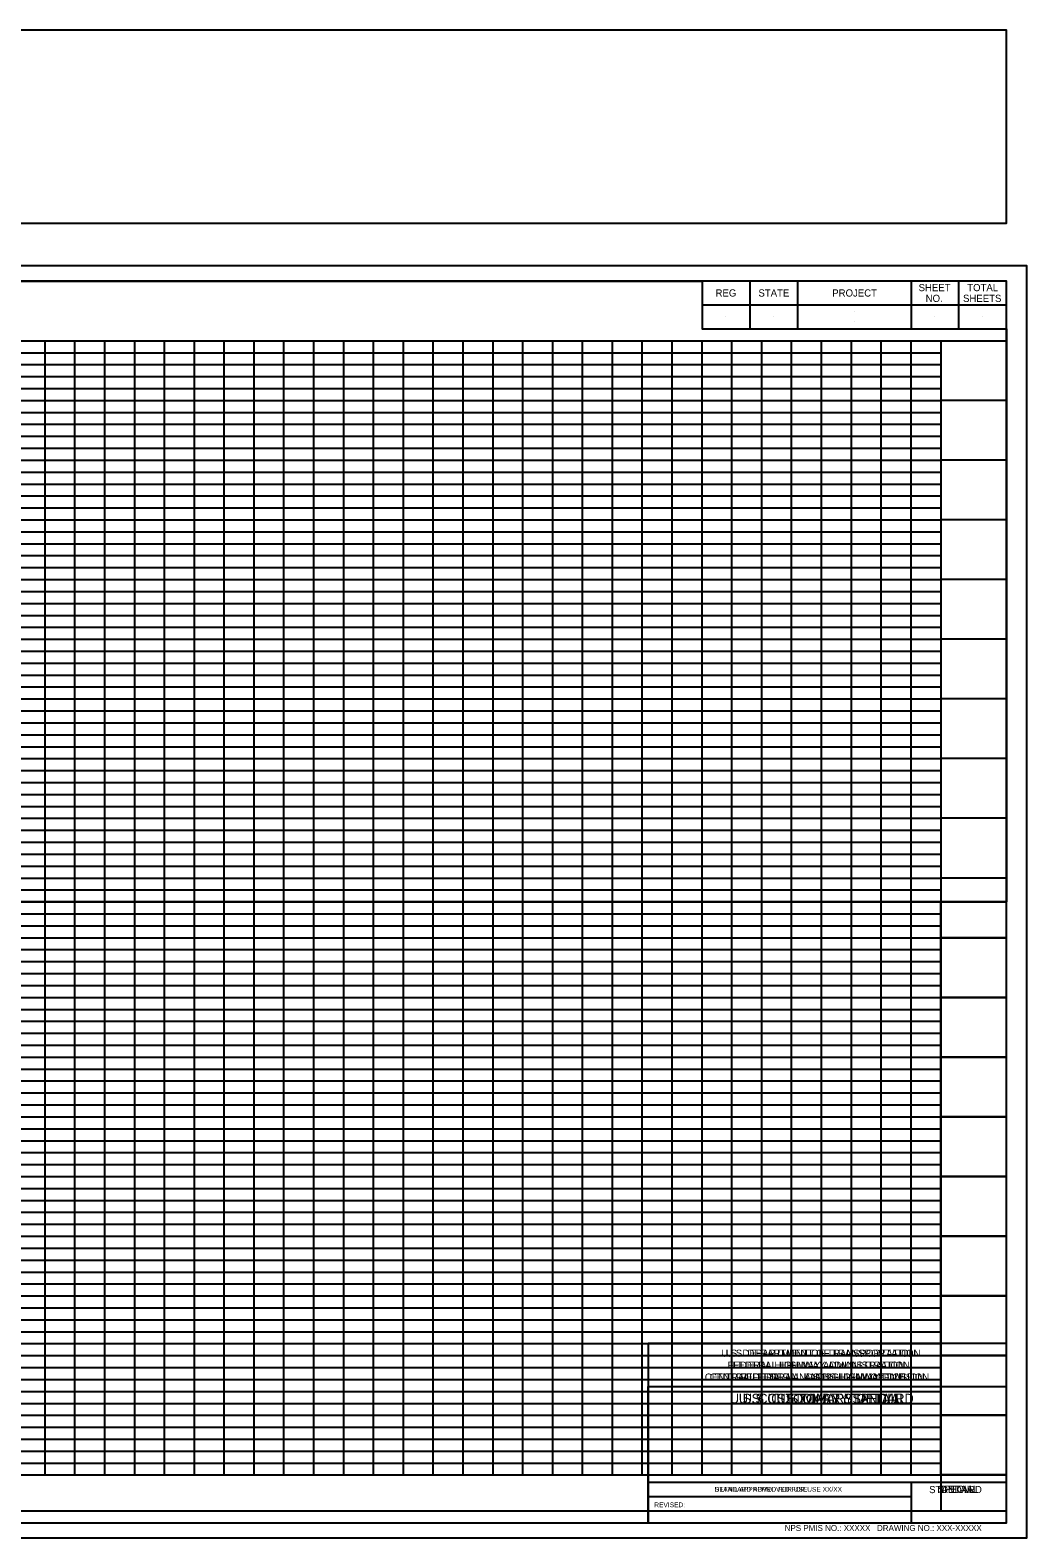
# Model space of a CAD drawing. Extents: x -87 to 1577, y -13 to 1250.
# Drawn here: x 742 to 1577, y -13 to 1250 of the extents above; entities that cross this region are included whole.
import ezdxf

# ---------------------------------------------------------------- set-up
doc = ezdxf.new("R2010")
doc.units = 0
for name, color, linetype in [('D_CFL_Clip_Boundary_1', 7, 'Continuous'), ('D_CFL_Clip_Boundary_2', 7, 'Continuous'), ('D_CFL_Sheet_Border_ PlotShape', 7, 'Continuous'), ('D_CFL_Sheet_Border_Base', 7, 'Continuous'), ('D_CFL_Sheet_Border_Box', 7, 'Continuous'), ('D_CFL_Sheet_Border_Detail', 7, 'Continuous'), ('D_CFL_Sheet_Border_General', 7, 'Continuous'), ('D_CFL_Sheet_Border_NPS_Pkg', 7, 'Continuous'), ('D_CFL_Sheet_Border_Plan_Plan', 7, 'Continuous'), ('D_CFL_Sheet_Border_PnP', 7, 'Continuous'), ('D_CFL_Sheet_Border_Profile', 7, 'Continuous'), ('D_CFL_Sheet_Border_Project_Info', 7, 'Continuous'), ('D_CFL_Sheet_Border_Special', 7, 'Continuous'), ('D_CFL_Sheet_Border_Standard', 7, 'Continuous')]:
    doc.layers.add(name, color=color, linetype=linetype)

msp = doc.modelspace()

# ---------------------------------------------------------------- linework, layer by layer
at = {"layer": 'D_CFL_Clip_Boundary_1'}
msp.add_lwpolyline([(0, 520), (0, 1040), (1305, 1040), (1305, 1000), (1560, 1000), (1560, 520)], close=True, dxfattribs=at)
at = {"layer": 'D_CFL_Clip_Boundary_2'}
msp.add_lwpolyline([(1505, 520), (55, 520), (55, 40), (1505, 40)], close=True, dxfattribs=at)
at = {"layer": 'D_CFL_Sheet_Border_ PlotShape'}
msp.add_line((1576.9, 1052.6), (1576.9, 1052.6), dxfattribs=at)
msp.add_lwpolyline([(-86.9, -12.7), (1576.9, -12.7), (1576.9, 1052.6), (-86.9, 1052.6)], close=True, dxfattribs=at)
at = {"layer": 'D_CFL_Sheet_Border_Base'}
for p, q in [((1345, 1040), (1345, 1000)), ((1385, 1040), (1385, 1000)), ((1480, 1040), (1480, 1000)), ((1520, 1000), (1520, 1040)), ((1305, 1020), (1560, 1020))]:
    msp.add_line(p, q, dxfattribs=at)
for points in [[(362.6, 1088.6), (1560, 1088.6), (1560, 1250.1), (362.6, 1250.1)], [(0, 0), (1560, 0), (1560, 1040), (0, 1040)]]:
    msp.add_lwpolyline(points, close=True, dxfattribs=at)
msp.add_lwpolyline([(1305, 1040), (1305, 1000), (1560, 1000)], dxfattribs=at)
at = {"layer": 'D_CFL_Sheet_Border_Box'}
for p, q in [((1260, 0), (1260, 114)), ((1260, 114), (1560, 114)), ((1410, 57), (1410, 57))]:
    msp.add_line(p, q, dxfattribs=at)
at = {"layer": 'D_CFL_Sheet_Border_Detail'}
for p, q in [((1260, 114), (1560, 114)), ((1410, 69), (1410, 69)), ((1260, 34), (1560, 34)), ((1480, 34), (1480, 0)), ((1260, 22), (1480, 22))]:
    msp.add_line(p, q, dxfattribs=at)
msp.add_lwpolyline([(1560, 150), (1260, 150), (1260, 0)], dxfattribs=at)
at = {"layer": 'D_CFL_Sheet_Border_General'}
for p, q in [((1260, 114), (1560, 114)), ((1410, 57), (1410, 57))]:
    msp.add_line(p, q, dxfattribs=at)
msp.add_lwpolyline([(1560, 150), (1260, 150), (1260, 0)], dxfattribs=at)
at = {"layer": 'D_CFL_Sheet_Border_Plan_Plan'}
for p, q in [((0, 520), (1560, 520)), ((1260, 0), (1260, 114)), ((1260, 114), (1560, 114)), ((1410, 57), (1410, 57))]:
    msp.add_line(p, q, dxfattribs=at)
at = {"layer": 'D_CFL_Sheet_Border_PnP'}
for p, q in [((0, 520), (1560, 520)), ((755, 40), (755, 520)), ((780, 40), (780, 520)), ((805, 40), (805, 520)), ((830, 40), (830, 520)), ((855, 40), (855, 520)), ((880, 40), (880, 520)), ((905, 40), (905, 520)), ((930, 40), (930, 520)), ((955, 40), (955, 520)), ((980, 40), (980, 520)), ((1005, 40), (1005, 520)), ((1030, 40), (1030, 520)), ((1055, 40), (1055, 520)), ((1080, 40), (1080, 520)), ((1105, 40), (1105, 520)), ((1130, 40), (1130, 520)), ((1155, 40), (1155, 520)), ((1180, 40), (1180, 520)), ((1205, 40), (1205, 520)), ((1230, 40), (1230, 520)), ((1255, 40), (1255, 520)), ((1280, 40), (1280, 520)), ((1305, 40), (1305, 520)), ((1330, 40), (1330, 520)), ((1355, 40), (1355, 520)), ((1380, 40), (1380, 520)), ((1405, 40), (1405, 520)), ((1430, 40), (1430, 520)), ((1455, 40), (1455, 520)), ((1480, 40), (1480, 520)), ((1505, 520), (1505, 10)), ((55, 510), (1505, 510)), ((55, 500), (1505, 500)), ((55, 490), (1505, 490)), ((55, 480), (1505, 480)), ((1505, 490), (1560, 490)), ((55, 470), (1505, 470)), ((55, 460), (1505, 460)), ((55, 450), (1505, 450)), ((55, 440), (1505, 440)), ((55, 430), (1505, 430)), ((1505, 440), (1560, 440)), ((55, 420), (1505, 420)), ((55, 410), (1505, 410)), ((55, 400), (1505, 400)), ((55, 390), (1505, 390)), ((55, 380), (1505, 380)), ((1505, 390), (1560, 390)), ((55, 370), (1505, 370)), ((55, 360), (1505, 360)), ((55, 350), (1505, 350)), ((55, 340), (1505, 340)), ((55, 330), (1505, 330)), ((1505, 340), (1560, 340)), ((55, 320), (1505, 320)), ((55, 310), (1505, 310)), ((55, 300), (1505, 300)), ((55, 290), (1505, 290)), ((55, 280), (1505, 280)), ((1505, 290), (1560, 290)), ((55, 270), (1505, 270)), ((55, 260), (1505, 260)), ((55, 250), (1505, 250)), ((55, 240), (1505, 240)), ((1505, 240), (1560, 240)), ((55, 230), (1505, 230)), ((55, 220), (1505, 220)), ((55, 210), (1505, 210)), ((55, 200), (1505, 200)), ((55, 190), (1505, 190)), ((1505, 190), (1560, 190)), ((55, 180), (1505, 180)), ((55, 170), (1505, 170)), ((55, 160), (1505, 160)), ((55, 150), (1505, 150)), ((55, 140), (1505, 140)), ((1505, 140), (1560, 140)), ((55, 130), (1505, 130)), ((55, 120), (1505, 120)), ((55, 110), (1505, 110)), ((55, 100), (1505, 100)), ((55, 90), (1505, 90)), ((1505, 90), (1560, 90)), ((55, 80), (1505, 80)), ((55, 70), (1505, 70)), ((55, 60), (1505, 60)), ((55, 50), (1505, 50)), ((55, 40), (1505, 40)), ((1505, 40), (1560, 40)), ((0, 10), (1560, 10))]:
    msp.add_line(p, q, dxfattribs=at)
at = {"layer": 'D_CFL_Sheet_Border_Profile'}
for p, q in [((0, 990), (1560, 990)), ((755, 40), (755, 990)), ((780, 40), (780, 990)), ((805, 40), (805, 990)), ((830, 40), (830, 990)), ((855, 40), (855, 990)), ((880, 40), (880, 990)), ((905, 40), (905, 990)), ((930, 40), (930, 990)), ((955, 40), (955, 990)), ((980, 40), (980, 990)), ((1005, 40), (1005, 990)), ((1030, 40), (1030, 990)), ((1055, 40), (1055, 990)), ((1080, 40), (1080, 990)), ((1105, 40), (1105, 990)), ((1130, 40), (1130, 990)), ((1155, 40), (1155, 990)), ((1180, 40), (1180, 990)), ((1205, 40), (1205, 990)), ((1230, 40), (1230, 990)), ((1255, 40), (1255, 990)), ((1280, 40), (1280, 990)), ((1305, 40), (1305, 990)), ((1330, 40), (1330, 990)), ((1355, 40), (1355, 990)), ((1380, 40), (1380, 990)), ((1405, 40), (1405, 990)), ((1430, 40), (1430, 990)), ((1455, 40), (1455, 990)), ((1480, 40), (1480, 990)), ((1505, 990), (1505, 10)), ((55, 980), (1505, 980)), ((55, 970), (1505, 970)), ((55, 960), (1505, 960)), ((55, 950), (1505, 950)), ((55, 940), (1505, 940)), ((1560, 940), (1505, 940)), ((55, 930), (1505, 930)), ((55, 920), (1505, 920)), ((55, 910), (1505, 910)), ((55, 900), (1505, 900)), ((55, 890), (1505, 890)), ((1560, 890), (1505, 890)), ((55, 880), (1505, 880)), ((55, 870), (1505, 870)), ((55, 860), (1505, 860)), ((55, 850), (1505, 850)), ((55, 840), (1505, 840)), ((1560, 840), (1505, 840)), ((55, 830), (1505, 830)), ((55, 820), (1505, 820)), ((55, 810), (1505, 810)), ((55, 800), (1505, 800)), ((55, 790), (1505, 790)), ((1560, 790), (1505, 790)), ((55, 780), (1505, 780)), ((55, 770), (1505, 770)), ((55, 760), (1505, 760)), ((55, 750), (1505, 750)), ((55, 740), (1505, 740)), ((1560, 740), (1505, 740)), ((55, 730), (1505, 730)), ((55, 720), (1505, 720)), ((55, 710), (1505, 710)), ((55, 700), (1505, 700)), ((55, 690), (1505, 690)), ((1560, 690), (1505, 690)), ((55, 680), (1505, 680)), ((55, 670), (1505, 670)), ((55, 660), (1505, 660)), ((55, 650), (1505, 650)), ((55, 640), (1505, 640)), ((1560, 640), (1505, 640)), ((55, 630), (1505, 630)), ((55, 620), (1505, 620)), ((55, 610), (1505, 610)), ((55, 600), (1505, 600)), ((55, 590), (1505, 590)), ((1560, 590), (1505, 590)), ((55, 580), (1505, 580)), ((55, 570), (1505, 570)), ((55, 560), (1505, 560)), ((55, 550), (1505, 550)), ((55, 540), (1505, 540)), ((1560, 540), (1505, 540)), ((55, 530), (1505, 530)), ((55, 520), (1505, 520)), ((55, 510), (1505, 510)), ((55, 500), (1505, 500)), ((55, 490), (1505, 490)), ((55, 480), (1505, 480)), ((1560, 490), (1505, 490)), ((55, 470), (1505, 470)), ((55, 460), (1505, 460)), ((55, 450), (1505, 450)), ((55, 440), (1505, 440)), ((55, 430), (1505, 430)), ((1560, 440), (1505, 440)), ((55, 420), (1505, 420)), ((55, 410), (1505, 410)), ((55, 400), (1505, 400)), ((55, 390), (1505, 390)), ((55, 380), (1505, 380)), ((1560, 390), (1505, 390)), ((55, 370), (1505, 370)), ((55, 360), (1505, 360)), ((55, 350), (1505, 350)), ((55, 340), (1505, 340)), ((55, 330), (1505, 330)), ((1560, 340), (1505, 340)), ((55, 320), (1505, 320)), ((55, 310), (1505, 310)), ((55, 300), (1505, 300)), ((55, 290), (1505, 290)), ((55, 280), (1505, 280)), ((1560, 290), (1505, 290)), ((55, 270), (1505, 270)), ((55, 260), (1505, 260)), ((55, 250), (1505, 250)), ((55, 240), (1505, 240)), ((1560, 240), (1505, 240)), ((55, 230), (1505, 230)), ((55, 220), (1505, 220)), ((55, 210), (1505, 210)), ((55, 200), (1505, 200)), ((55, 190), (1505, 190)), ((1560, 190), (1505, 190)), ((55, 180), (1505, 180)), ((55, 170), (1505, 170)), ((55, 160), (1505, 160)), ((55, 150), (1505, 150)), ((55, 140), (1505, 140)), ((1560, 140), (1505, 140)), ((55, 130), (1505, 130)), ((55, 120), (1505, 120)), ((55, 110), (1505, 110)), ((55, 100), (1505, 100)), ((55, 90), (1505, 90)), ((1560, 90), (1505, 90)), ((55, 80), (1505, 80)), ((55, 70), (1505, 70)), ((55, 60), (1505, 60)), ((55, 50), (1505, 50)), ((55, 40), (1505, 40)), ((1560, 40), (1505, 40)), ((0, 10), (1560, 10))]:
    msp.add_line(p, q, dxfattribs=at)
at = {"layer": 'D_CFL_Sheet_Border_Project_Info'}
for p, q in [((1432.5, 1014.7), (1432.5, 1014.7)), ((1325, 1010), (1325, 1010)), ((1365, 1010), (1365, 1010)), ((1432.5, 1005.7), (1432.5, 1005.7)), ((1500, 1010), (1500, 1010)), ((1540, 1010), (1540, 1010))]:
    msp.add_line(p, q, dxfattribs=at)
at = {"layer": 'D_CFL_Sheet_Border_Special'}
for p, q in [((1260, 114), (1560, 114)), ((1410, 69), (1410, 69)), ((1260, 34), (1560, 34)), ((1480, 34), (1480, 0)), ((1260, 22), (1480, 22))]:
    msp.add_line(p, q, dxfattribs=at)
msp.add_lwpolyline([(1560, 150), (1260, 150), (1260, 0)], dxfattribs=at)
at = {"layer": 'D_CFL_Sheet_Border_Standard'}
for p, q in [((1260, 114), (1560, 114)), ((1410, 69), (1410, 69)), ((1260, 34), (1560, 34)), ((1480, 34), (1480, 0)), ((1260, 22), (1480, 22))]:
    msp.add_line(p, q, dxfattribs=at)
msp.add_lwpolyline([(1560, 150), (1260, 150), (1260, 0)], dxfattribs=at)

# ---------------------------------------------------------------- texts
at = {"layer": 'D_CFL_Sheet_Border_Base'}
for s, p in [('SHEET', (1486.3, 1031.5)), ('TOTAL', (1527, 1031.5)), ('REG', (1316.3, 1027)), ('STATE', (1352.2, 1027)), ('PROJECT', (1414, 1027)), ('NO.', (1492.2, 1022.5)), ('SHEETS', (1523.5, 1022.5))]:
    msp.add_text(s, height=6, dxfattribs=at).set_placement(p)
at = {"layer": 'D_CFL_Sheet_Border_Detail'}
for s, height, p in [('U.S. DEPARTMENT OF TRANSPORTATION', 6, (1321, 139)), ('FEDERAL HIGHWAY ADMINISTRATION', 6, (1326.4, 129)), ('CENTRAL FEDERAL LANDS HIGHWAY DIVISION', 6, (1307.3, 119)), ('U.S. CUSTOMARY DETAIL', 8, (1339.1, 100)), ('DETAIL APPROVED FOR USE', 4, (1315.5, 26)), ('DETAIL', 6, (1505.1, 25)), ('REVISED:                                                 ', 4, (1265, 13))]:
    msp.add_text(s, height=height, dxfattribs=at).set_placement(p)
at = {"layer": 'D_CFL_Sheet_Border_General'}
for s, p in [('U.S. DEPARTMENT OF TRANSPORTATION', (1325.2, 139)), ('FEDERAL HIGHWAY ADMINISTRATION', (1330.6, 129)), ('CENTRAL FEDERAL LANDS HIGHWAY DIVISION', (1311.5, 119))]:
    msp.add_text(s, height=6, dxfattribs=at).set_placement(p)
at = {"layer": 'D_CFL_Sheet_Border_NPS_Pkg'}
msp.add_text('NPS PMIS NO.: XXXXX   DRAWING NO.: XXX-XXXXX ', height=5, dxfattribs=at).set_placement((1374.2, -6.9))
at = {"layer": 'D_CFL_Sheet_Border_Special'}
for s, height, p in [('U.S. DEPARTMENT OF TRANSPORTATION', 6, (1325.2, 139)), ('FEDERAL HIGHWAY ADMINISTRATION', 6, (1330.6, 129)), ('CENTRAL FEDERAL LANDS HIGHWAY DIVISION', 6, (1311.5, 119)), ('U.S. CUSTOMARY SPECIAL', 8, (1335.8, 100)), ('SPECIAL', 6, (1502.4, 25))]:
    msp.add_text(s, height=height, dxfattribs=at).set_placement(p)
at = {"layer": 'D_CFL_Sheet_Border_Standard'}
for s, height, p in [('U.S. DEPARTMENT OF TRANSPORTATION', 6, (1325.2, 139)), ('FEDERAL HIGHWAY ADMINISTRATION', 6, (1330.6, 129)), ('FEDERAL LANDS HIGHWAY OFFICE', 6, (1337.2, 119)), ('U.S. CUSTOMARY STANDARD', 8, (1328.3, 100)), ('STANDARD APPROVED FOR USE XX/XX', 4, (1315.7, 26)), ('STANDARD', 6, (1495.1, 24.8)), ('REVISED:                                                 ', 4, (1265, 13))]:
    msp.add_text(s, height=height, dxfattribs=at).set_placement(p)

doc.saveas('drawing.dxf')
